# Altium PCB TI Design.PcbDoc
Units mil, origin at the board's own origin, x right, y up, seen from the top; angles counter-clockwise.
Board outline 3200 x 1800 mil, 4 copper layers (Top Layer, GND, Power Supply, Bottom Layer), stack 90 mil thick; 62 components, 53 nets, 248 pads, 98 vias.
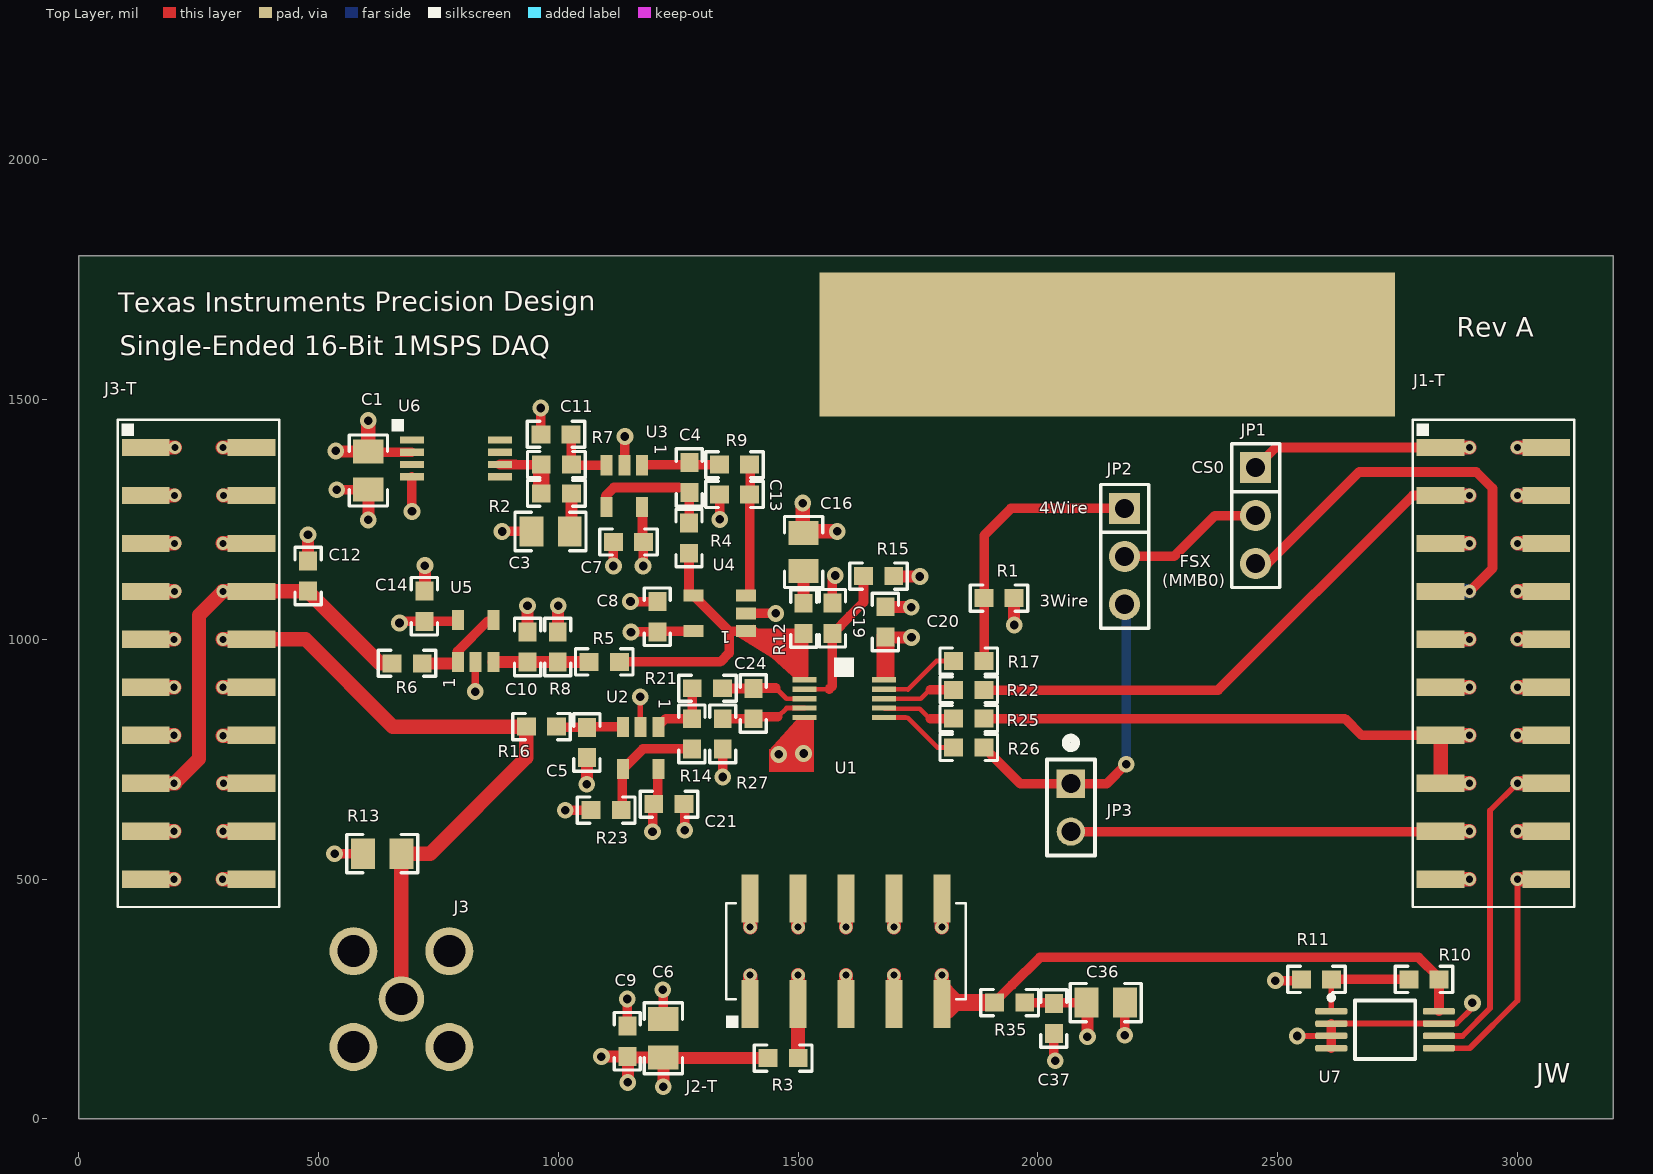
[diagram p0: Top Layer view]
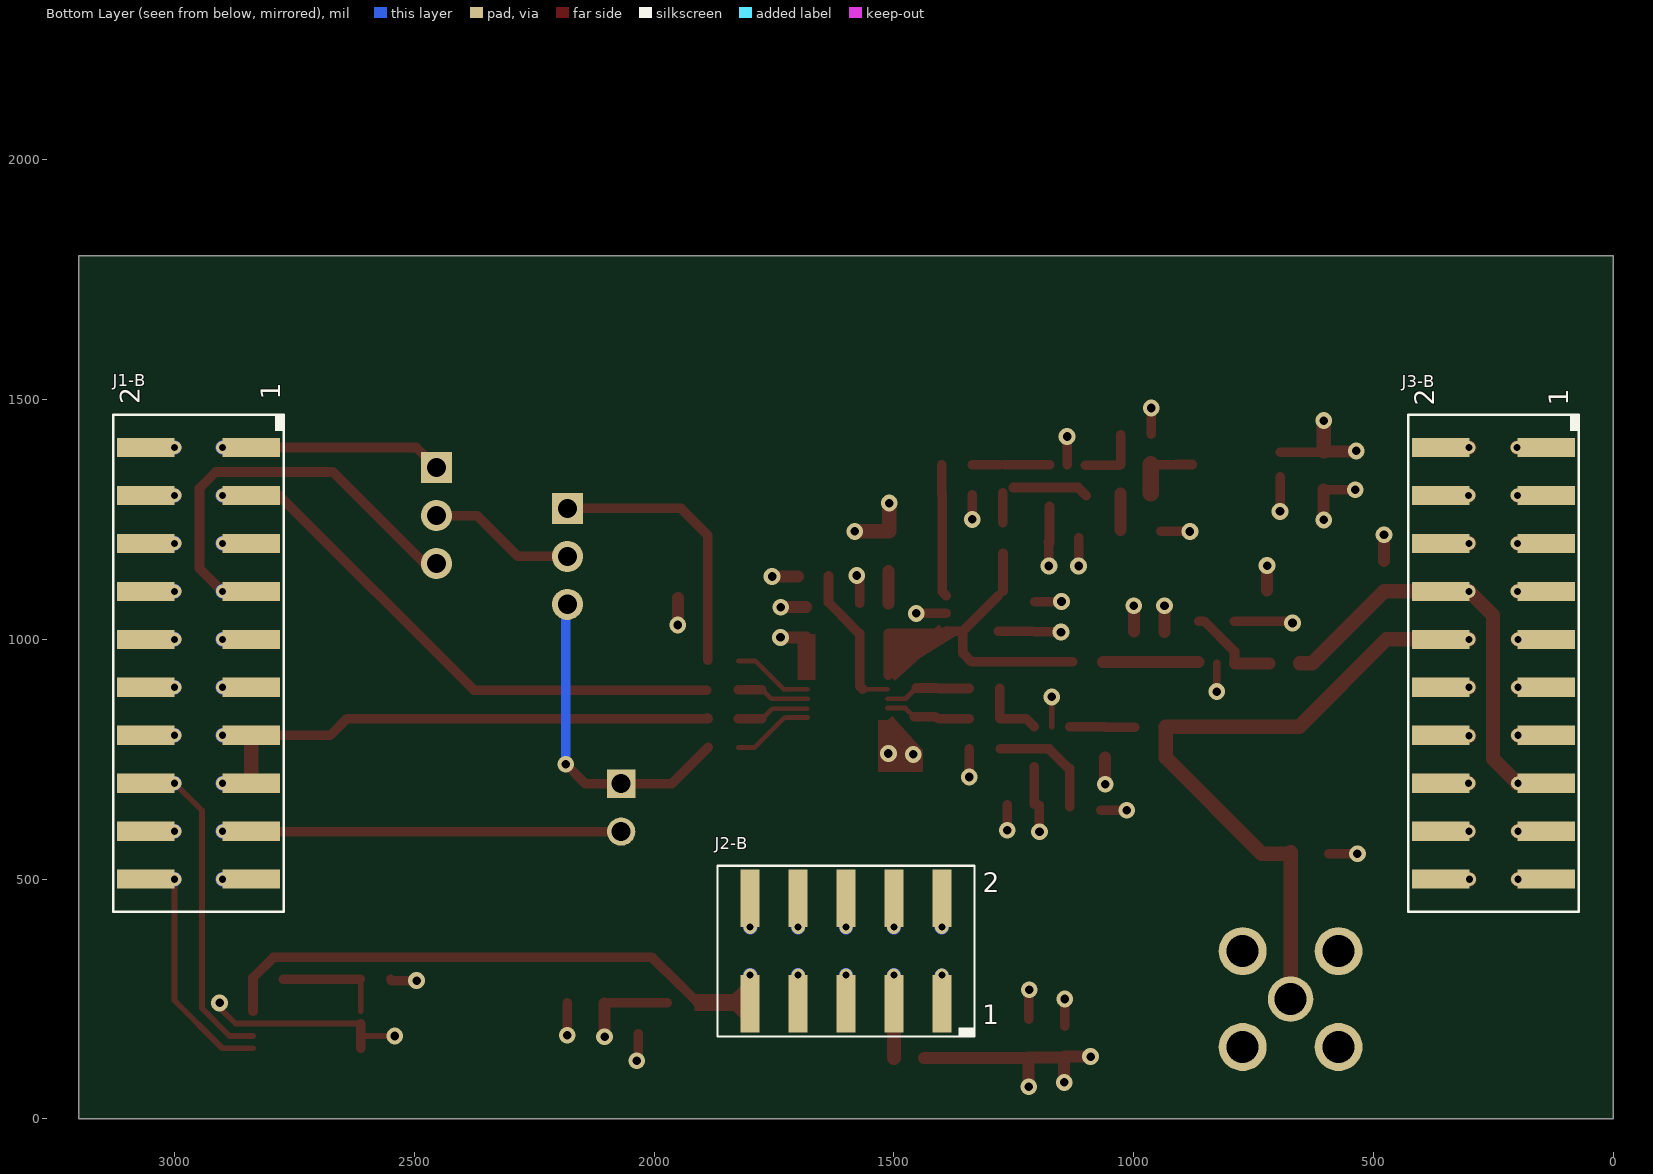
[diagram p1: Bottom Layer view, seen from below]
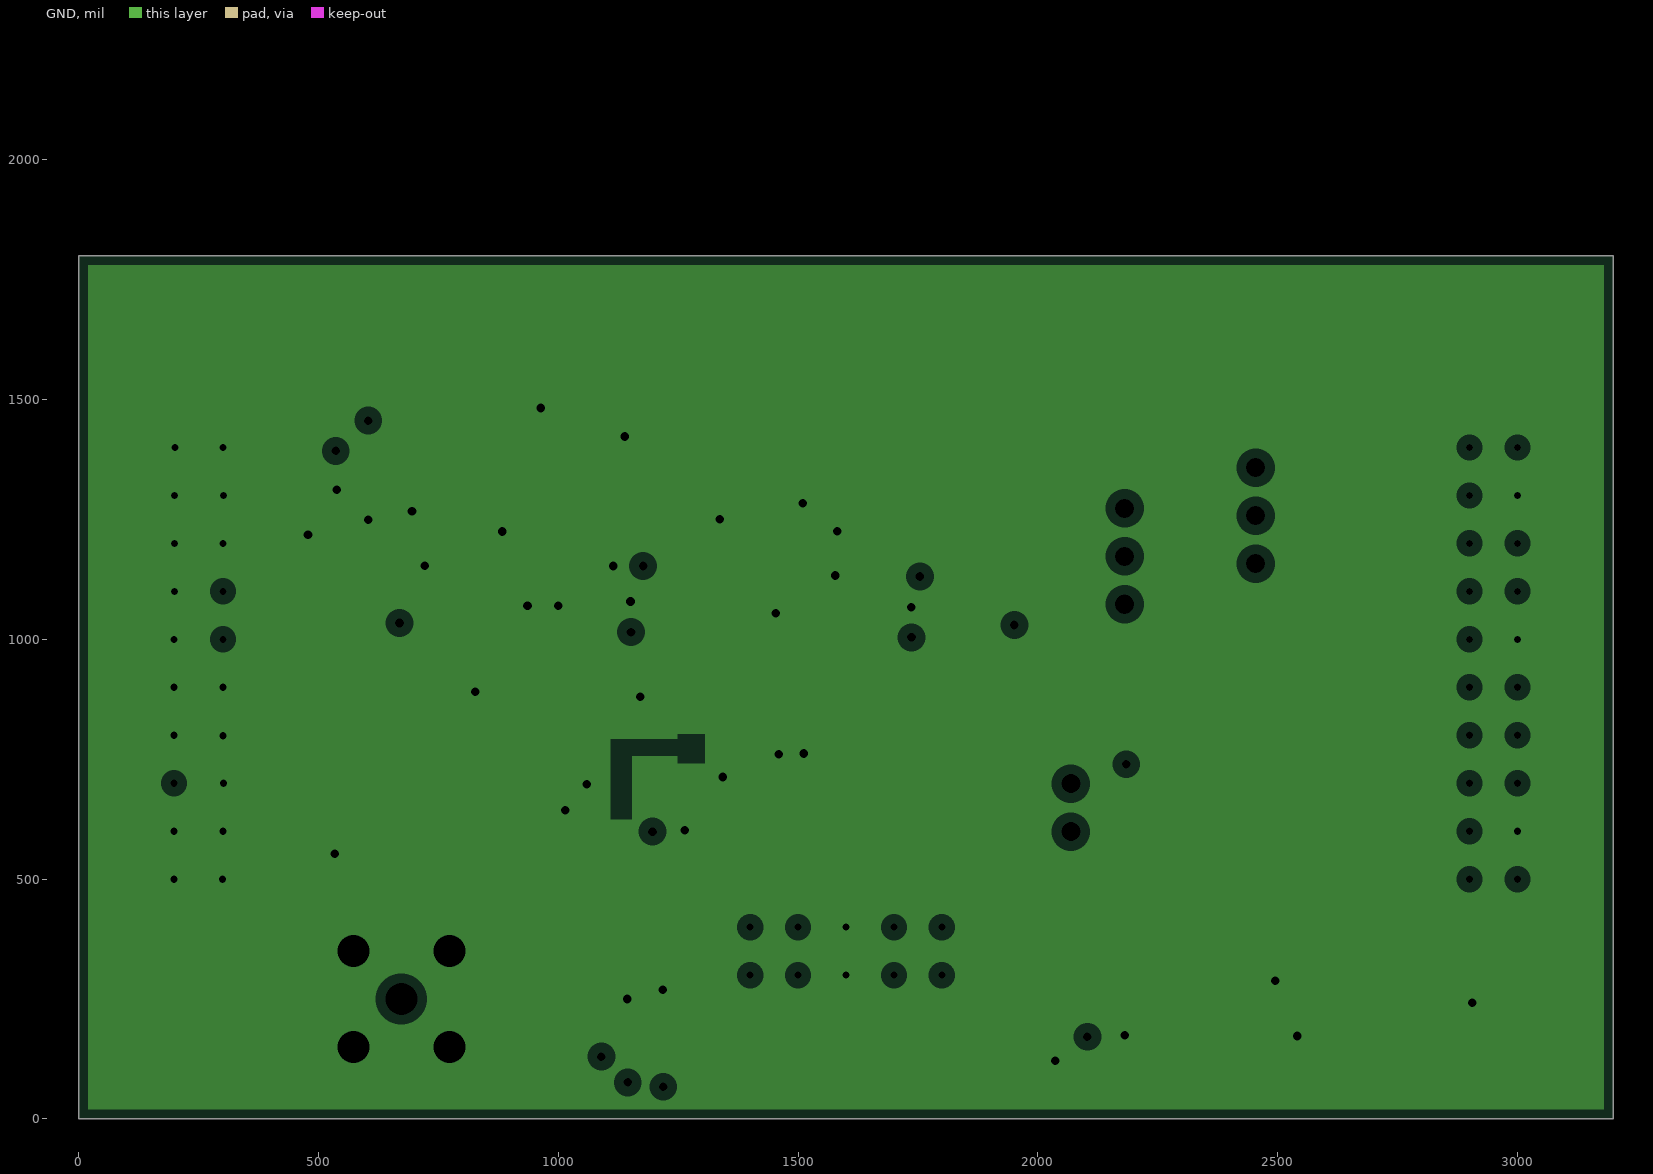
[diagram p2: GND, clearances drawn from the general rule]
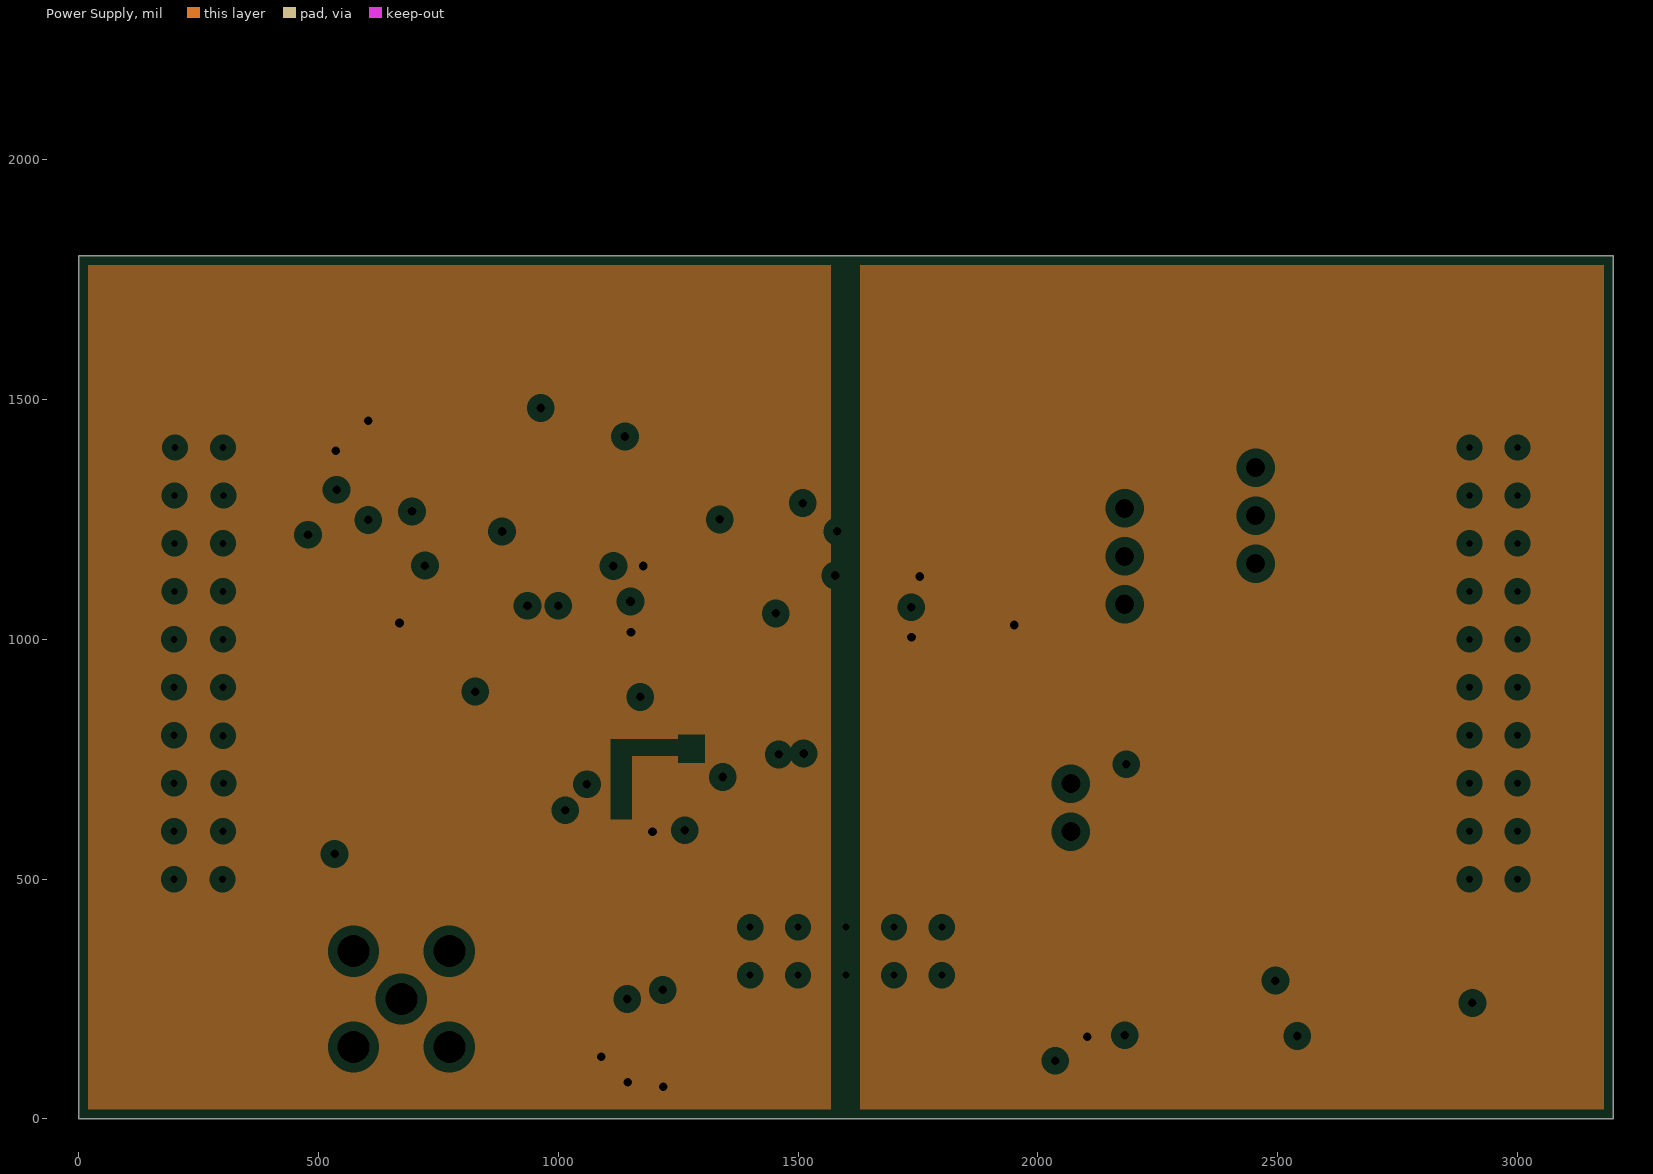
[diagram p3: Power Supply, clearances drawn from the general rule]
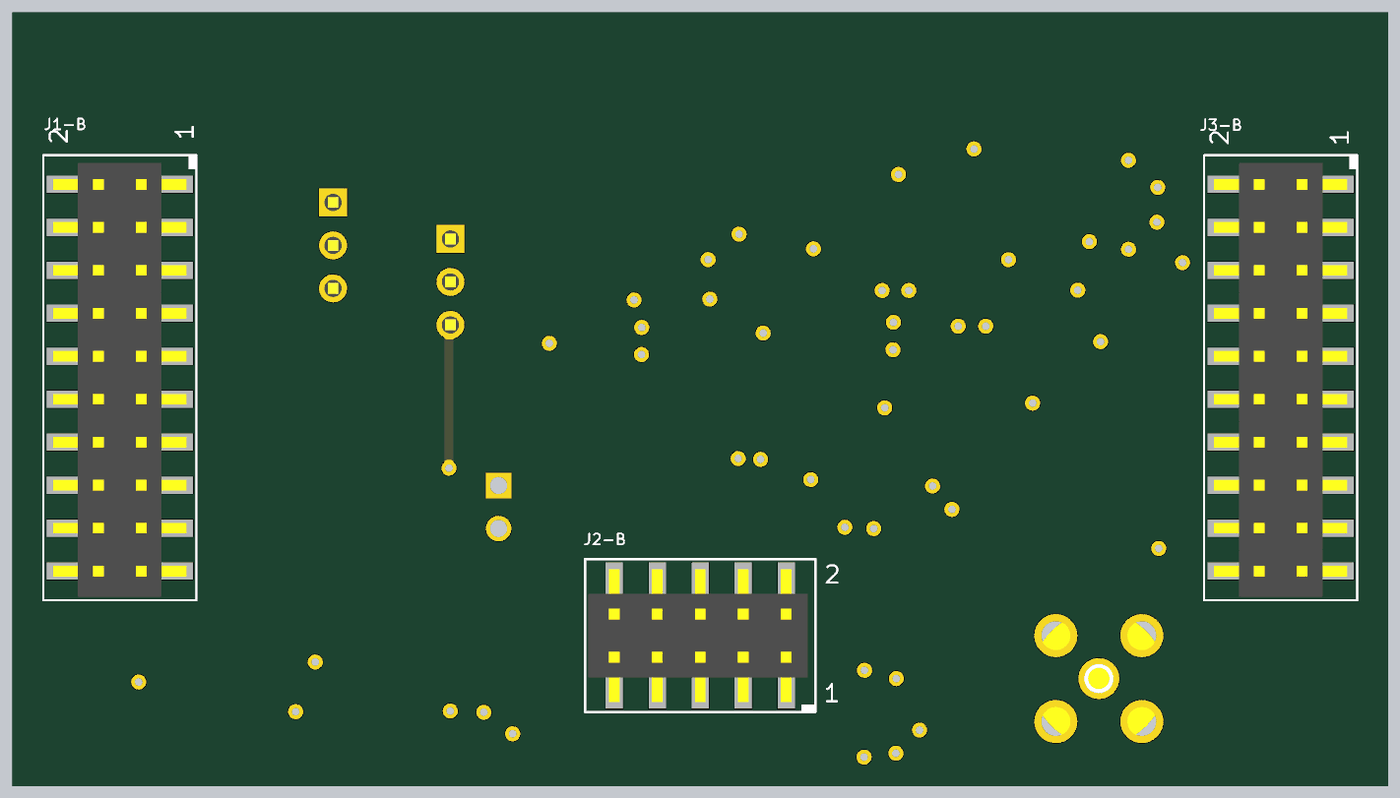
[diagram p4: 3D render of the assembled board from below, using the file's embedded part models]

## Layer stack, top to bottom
Top Layer: signal copper 1.4
Dielectric: core 59.2, FR-4, Dk 4.8
GND: plane copper 1.4, net GND
Dielectric: prepreg 12.6, FR-4, Dk 4.8
Power Supply: plane copper 1.4, net (Multiple Nets)
Dielectric: core 12.6, FR-4, Dk 4.8
Bottom Layer: signal copper 1.4

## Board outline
0,0 0,1800 3200,1800 3200,0 0,0

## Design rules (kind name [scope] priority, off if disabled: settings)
AcuteAngle [All] p1: minimum=4.50000000000000E+0001 checktracksonly=FALSE
AssemblyTestPointUsage [All] p1: valid=2
Clearance Clearance_BoardEdge_MountingHoles [OnCopper and InComponentClass('Mounting Holes') vs IsKeepOut] p1: gap=40
Clearance Clearance_BoardEdge_Poly [OnCopper and InPoly vs IsKeepOut] p2: gap=25
Clearance Clearance_BoardEdge [OnCopper and Not InComponentClass('Logo') and not InComponentClass('FiducialMark') and not InRegion(1000,500,4000,800) and Not IsKeepout vs IsKeepOut] p3: gap=75
Clearance Clearance_Poly [InPolygon] p4: gap=25
Clearance [All] p5: gap=8
ComponentClearance ComponentClearance_Shunt [InComponentClass('Header') vs InComponentClass('Shunt')] p1: gap=0 collisioncheckmode=3 verticalgap=0 showdistances=FALSE
ComponentClearance ComponentClearance_Logo [InComponentClass('Logo')] p2: gap=50 collisioncheckmode=3 verticalgap=10 showdistances=FALSE
ComponentClearance ComponentClearance_ScrewToNut [(HasFootprint('NY PMS 440 0025 PH')) vs (HasFootprint('Keystone_1902C'))] p3: gap=5 collisioncheckmode=3 verticalgap=10 showdistances=FALSE
ComponentClearance ComponentClearance_MountingHoles [InComponentClass('Mounting Holes')] p4: gap=250 collisioncheckmode=3 verticalgap=100000 showdistances=FALSE
ComponentClearance ComponentClearance_SmallPassives [HasFootprint('0201*') or HasFootprint('0402*') or HasFootprint('0508') or HasFootprint('0603*') or HasFootprint('0612') or HasFootprint('0805*') or HasFootprint('0815*') or HasFootprint('0830*') or HasFootprint('1206*') or HasFootprint('1210*') or HasFootprint('1808*') or HasFootprint('1812*') or HasFootprint('1825*') or HasFootprint('2010*') or HasFootprint('2220*') or HasFootprint('2225*') or HasFootprint('2512*') or HasFootprint('2728*') or HasFootprint('3518*') vs HasFootprint('0201*') or HasFootprint('0402*') or HasFootprint('0508') or HasFootprint('0603*') or HasFootprint('0612') or HasFootprint('0805*') or HasFootprint('0815*') or HasFootprint('0830*') or HasFootprint('1206*') or HasFootprint('1210*') or HasFootprint('1808*') or HasFootprint('1812*') or HasFootprint('1825*') or HasFootprint('2010*') or HasFootprint('2220*') or HasFootprint('2225*') or HasFootprint('2512*') or HasFootprint('2728*') or HasFootprint('3518*')] p5: gap=20 collisioncheckmode=3 verticalgap=10 showdistances=FALSE
ComponentClearance ComponentClearance_THtoSMT [IsThruComponent vs IsSMTComponent] p6: gap=100 collisioncheckmode=3 verticalgap=30 showdistances=FALSE
ComponentClearance ComponentClearance_THtoTH [IsThruComponent vs IsThruComponent] p7: gap=118.11 collisioncheckmode=3 verticalgap=30 showdistances=FALSE
ComponentClearance [All] p8 off: gap=40 collisioncheckmode=3 verticalgap=10 showdistances=FALSE
DiffPairsRouting [All] p1: maxlimit=100 minlimit=10 mostfreqgap=10 maxuncoupledlength=1000
FabricationTestPointUsage TestPointUsage [All] p1: valid=2 allowmultiple=FALSE
FabricationTestpoint Testpoint [All] p1: side=3 testpointundercomponent=TRUE minsize=40 maxsize=100 preferedsize=60 minholesize=0 maxholesize=40 preferedholesize=32 testpointgrid=1 allowsidetop=TRUE allowsidebottom=TRUE usegrid=TRUE gridtolerance=0.01
FanoutControl Fanout_LCC [IsLCC] p1: bgadir=Out bgaviamode=Centered fanoutstyle=Auto fanoutdirection=Alternating viagrid=1 // Fanout_LCC (Default Rule)
FanoutControl Fanout_BGA [IsBGA] p2: bgadir=Out bgaviamode=Centered fanoutstyle=Auto fanoutdirection=Alternating viagrid=1 // Fanout_BGA (Default Rule)
FanoutControl Fanout_Default [All] p4: bgadir=Out bgaviamode=Centered fanoutstyle=Auto fanoutdirection=Alternating viagrid=1 // Fanout_Default (Default Rule)
FanoutControl Fanout_Small [(CompPinCount < 5)] p5: bgadir=Out bgaviamode=Centered fanoutstyle=Auto fanoutdirection=OutThenIn viagrid=1 // Fanout_Small (Default Rule)
HoleSize [All] p1: absolutevalues=TRUE maxlimit=251 minlimit=7.8 maxpercent=80.000 minpercent=20.000
MinimumAnnularRing MinimumAnnularRing_ThermalPadVias [IsVia and InAnyComponent] p1: minimumring=5.91
MinimumAnnularRing [All] p2: minimumring=6
MinimumSolderMaskSliver MinimumSolderMaskSliver_Logo [InComponentClass('Logo') vs InComponentClass('Logo')] p1: minsoldermaskwidth=0.7
MinimumSolderMaskSliver [All] p2: minsoldermaskwidth=3.94
PlaneClearance [All] p1: clearance=20
PlaneConnect [All] p1: planeconnectstyle=Direct reliefexpansion=10 reliefentries=4 reliefconductorwidth=10 reliefairgap=10
PolygonConnect [All] p1: connectstyle=Relief reliefconductorwidth=10 reliefentries=4 polygonreliefangle="90 Angle" airgapwidth=10
RoutingVias ThermalPadVias [IsVia and InAnyComponent] p1: holewidth=18 width=35 viastyle="Through Hole" minholewidth=7.87 minwidth=19.68 maxholewidth=20 maxwidth=40
RoutingVias [All] p2: holewidth=18 width=35 viastyle="Through Hole" minholewidth=7.87 minwidth=20 maxholewidth=40 maxwidth=65
SMDToCorner [All] p1: distance=30000
SilkToSilkClearance [All] p1: silktosilkclearance=5
SilkscreenOverComponentPads [All] p1: minsilkscreentomaskgap=5
SolderMaskExpansion [All] p1: expansion=1.97
Width [All] p1: maxlimit=100 minlimit=6 preferedwidth=10 checkconnectedcopper=TRUE
13 further rules are at their usual default settings.

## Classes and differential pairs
component class Logo: Logo1 "Texas Instruments Precision Design"
component class Header: JP1 JP2

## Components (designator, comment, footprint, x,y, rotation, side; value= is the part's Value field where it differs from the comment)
C1 "C0805C105K8RACTU" 0805_HV 604,1352 r270 top
C3 "GRM21BR70J106KE76L" 0805_HV 984,1225 r180 top
C4 "GRM188R70J105KA01D" 0603 1273.34,1337.48 r270 top
C5 "GRM1885C1E102JA01D" 0603 1059.68,785.05 r270 top
C6 "GRM21BR61E106MA73" 0805_HV 1219,168 r90 top
C7 "0603YC104JAT2A" 0603 1146.57,1203 r180 top
C8 "0603YC104JAT2A" 0603 1206.68,1047.05 r90 top
C9 "C0603C102J5GAC" 0603 1144,162 r270 top
C10 "GRM188R70J105KA01D" 0603 936,984 r270 top
C11 "GRM188R70J105KA01D" 0603 995.5,1427.45 r0 top
C12 "GRM188R70J105KA01D" 0603 478.32,1132 r270 top
C13 "GRM188R70J105KA01D" 0603 1367.68,1302.05 r0 top
C14 "0603YC104JAT2A" 0603 721,1069 r90 top
C16 "GRM21BR71A106KE51L" 0805_HV 1511.68,1182.05 r270 top
C19 "GRM188R71E105KA12D" 0603 1571.68,1044.05 r270 top
C20 "GRM188R71E105KA12D" 0603 1682.08,1036.5 r270 top
C21 "0603YC104JAT2A" 0603 1230.68,656.25 r0 top
C24 "GRM1885C1E102JA01D" 0603 1406.68,866.05 r270 top
C36 "GRM21BR61E106MA73" 0805_HV 2141.3,242.55 r0 top
C37 "C0603C102J5GAC" 0603 2033.3,209.55 r90 top
J1-B "Bottom Side Connector" CONN_SSW-110-22-F-D-VS-K 2950,950 r90 bottom
J1-T "TSM-110-01-T-DV-P" CONN_TSM-110-01-T-DV-P 2950,950 r270 top
J2-B "SSW-105-22-F-D-VS-K" CONN_SSW-105-22-F-D-VS-K 1600,350 r180 bottom
J2-T "TSM-105-01-T-DV-P" CONN_TSM-105-01-T-DV-P 1600,350 r0 top
J3 "142-0701-201" Johnson_142-0701-20x 673,250 r0 top
J3-B "Bottom Side Connector" CONN_SSW-110-22-F-D-VS-K 250,950 r90 bottom
J3-T "TSM-110-01-T-DV-P" CONN_TSM-110-01-T-DV-P 250,950 r270 top
JP1 "PBC03SAAN" PBC03SAAN 2454,1258 r270 top
JP2 "PBC03SAAN" PBC03SAAN 2181,1173 r270 top
JP3 "5-146261-1" CONN_5-146261-1 2068.82,649.18 r270 top
R1 "CRCW060320K0FKEA" 0603 1919,1086 r180 top
R2 "CRCW060320K0FKEA" 0603 996,1304.46 r0 top
R3 "ERJ-3GEY0R00V" 0603 1469,127 r180 top
R4 "CRCW060320K0FKEA" 0603 1272.68,1211.05 r90 top
R5 "RG1608P-102-B-T5" 0603 1096,953 r0 top
R6 "RG1608P-102-B-T5" 0603 685,950 r0 top
R7 "RG1608P-102-B-T5" 0603 996,1364.46 r0 top
R8 "RG1608P-102-B-T5" 0603 999,984 r270 top
R9 "RG1608P-102-B-T5" 0603 1367.69,1364.22 r0 top
R10 "Uninstalled" 0603 2805,291 r0 top
R11 "RC0603FR-0747RL" 0603 2581,291 r180 top
R12 "ERJ-3RQFR22V" 0603 1511.68,1043.65 r270 top
R13 "RG2012P-510-B-T5" 0805_HV 633,553 r0 top
R14 "RC0603FR-0710RL" 0603 1278.68,803.05 r90 top
R15 "RC0603FR-0710RL" 0603 1668,1132 r0 top
R16 "RC0603FR-0710RL" 0603 965,818 r0 top
R17 "RC0603FR-0710RL" 0603 1856,954.7 r0 top
R21 "RC0603FR-0710RL" 0603 1311,898 r0 top
R22 "RC0603FR-0710RL" 0603 1856,894.7 r0 top
R23 "RC0603FR-0710RL" 0603 1100,644 r0 top
R25 "RC0603FR-0710RL" 0603 1856,834.7 r0 top
R26 "RC0603FR-0710RL" 0603 1856,774.7 r0 top
R27 "RC0603FR-0710RL" 0603 1343,803 r90 top
R35 "ERJ-3GEY0R00V" 0603 1941.3,242.55 r0 top
"Texas Instruments Precision Design" "Texas Instruments" TI_Stacked_SolderMask_Medium 2145,1615 r0 top (schematic designator Logo1)
U1 "ADS886XIDGS" DGS_10P2 1595.68,876.75 r0 top
U2 "OPA320AIDBV" SOT23-5P 1172,772 r270 top
U3 "OPA333AIDBV" SOT23-5P 1138,1318 r270 top
U4 "THS4281DBV" DBV-5 1336.68,1054.05 r180 top
U5 "OPA333AIDBV" SOT23-5P 828,998 r90 top
U6 "REF50XXAIDGK" DGK8 785,1376.8 r0 top
U7 "24LC256-I/ST" TSSOP-8 2724,186 r0 top

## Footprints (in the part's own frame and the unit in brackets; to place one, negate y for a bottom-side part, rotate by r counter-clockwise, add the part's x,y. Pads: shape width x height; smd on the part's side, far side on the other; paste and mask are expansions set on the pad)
0603 [mm] "0603 from SM-752 data"
  rect 1x0.95 smd: 1(-0.8,0) 2(0.8,0)
  silkscreen extent -1.52,-0.69 1.52,0.69, body extent -0.87,-0.47 0.87,0.47, height 0.85
0805_HV [mil] "0805 with 30mil clearance between pads"
  rect 50x63 smd: 1(-40,0) 2(40,0)
  silkscreen extent -74,-40 74,40, body extent -43,-29 43,29, height 43
CONN_5-146261-1 [mm] "Sullins"
  rect 1.5x1.5 hole 1.016: 1(-1.27,0)
  round 1.5 hole 1.016: 2(1.27,0)
  silkscreen extent -3.68,-1.27 2.54,1.27, body extent -2.51,-1.27 2.51,1.27, height 10.87
CONN_SSW-105-22-F-D-VS-K [mil]
  rect 40x120 smd: 1(200,-110) 2(200,110) 3(100,-110) 4(100,110) 5(0,-110) 6(0,110) 7(-100,-110) 8(-100,110) 9(-200,-110) 10(-200,110)
  silkscreen extent -268,-178 268,178, body extent -260,-155 250,155, height 435
CONN_SSW-110-22-F-D-VS-K [mil]
  rect 40x120 smd: 1(450,-110) 2(450,110) 3(350,-110) 4(350,110) 5(250,-110) 6(250,110) 7(150,-110) 8(150,110) 9(50,-110) 10(50,110) 11(-50,-110) 12(-50,110) 13(-150,-110) 14(-150,110) 15(-250,-110) 16(-250,110) 17(-350,-110) 18(-350,110) 19(-450,-110) 20(-450,110)
  silkscreen extent -518,-178 518,178, body extent -510,-155 500,155, height 435
CONN_TSM-105-01-T-DV-P [mil]
  rect 36x100 smd mask+2: 1(-200,-110) 2(-200,110) 3(-100,-110) 4(-100,110) 5(0,-110) 6(0,110) 7(100,-110) 8(100,110) 9(200,-110) 10(200,110)
  silkscreen extent -250,-160 250,100, body extent -250,-145 250,145, height 380
CONN_TSM-110-01-T-DV-P [mil]
  rect 36x100 smd mask+2: 1(-450,-110) 2(-450,110) 3(-350,-110) 4(-350,110) 5(-250,-110) 6(-250,110) 7(-150,-110) 8(-150,110) 9(-50,-110) 10(-50,110) 11(50,-110) 12(50,110) 13(150,-110) 14(150,110) 15(250,-110) 16(250,110) 17(350,-110) 18(350,110) 19(450,-110) 20(450,110)
  silkscreen extent -508,-168 508,168, body extent -500,-145 500,145, height 380
DBV-5 [mil]
  rect 42x25 smd: 1(-54.5,37) 2(-54.5,0) 3(-54.5,-37) 4(54.5,-37) 5(54.5,37)
DGK8 [mil]
  rect 50x15 smd: 1(-90.2,39) 2(-90.2,13.4) 3(-90.2,-12.2) 4(-90.2,-37.8) 5(93.4,-37.8) 6(93.4,-12.2) 7(93.4,13.4) 8(93.4,39)
  silkscreen extent -132,57 -107,82
DGS_10P2 [mil]
  rect 50x11 smd: 1(-82,39) 2(-82,19.3) 3(-82,-0.4) 4(-82,-20.1) 5(-82,-39.8) 6(84,-39.8) 7(84,-20.1) 8(84,-0.4) 9(84,19.3) 10(84,39)
  silkscreen extent -20,45 20,85
Johnson_142-0701-20x [mil] "Johnson Components recommended land pattern"
  round 95 hole 67: 1(0,0)
  round 100 hole 67: 2(100,100) 3(100,-100) 4(-100,-100) 5(-100,100)
  body extent -156,-156 156,156, height 375
PBC03SAAN [mm] "Sullins 100mil, 1x3, 230 mil above insulator"
  rect 1.65x1.65 hole 1.016: 1(-2.54,0)
  round 1.65 hole 1.016: 2(0,0) 3(2.54,0)
  silkscreen extent -3.81,-1.27 3.81,1.27, body extent -3.81,-1.27 3.81,1.27, height 8.38
SOT23-5P [mil]
  rect 42x25 smd: 1(-45,37) 2(-45,0) 3(-45,-37) 4(42,-37) 5(42,37)
TI_Stacked_SolderMask_Medium [mil]
  rect 1200x300 smd paste-196 mask-196: 0(0,0)
TSSOP-8 [mm] "TSSOP, 8-Leads, Body 3.1x4.5mm (max), Pitch 0.65mm, IPC Medium Density"
  rrect50% 1.7x0.35 smd: 1(-2.85,0.975) 2(-2.85,0.325) 3(-2.85,-0.325) 4(-2.85,-0.975) 5(2.85,-0.975) 6(2.85,-0.325) 7(2.85,0.325) 8(2.85,0.975)
  silkscreen extent -2.97,-1.55 1.6,1.82, body extent -3.2,-1.55 3.2,1.55, height 1.07

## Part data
C1: "CAP, CERM, 1uF, 10V, +/-10%, X7R, 0805"
C3: "CAP, CERM, 10uF, 6.3V, +/-10%, X7R, 0805"
C4 C10 C11 C12 C13: "CAP, CERM, 1uF, 6.3V, +/-10%, X7R, 0603"
C5 C24: "CAP, CERM, 1000pF, 25V, +/-5%, C0G/NP0, 0603"
C6 C36: "CAP, CERM, 10uF, 25V, +/-20%, X5R, 0805"
C7 C8 C14 C21: "CAP, CERM, 0.1uF, 16V, +/-5%, X7R, 0603"
C9 C37: "CAP, CERM, 1000pF, 50V, +/-5%, C0G/NP0, 0603"
C16: "CAP, CERM, 10uF, 10V, +/-10%, X7R, 0805"
C19 C20: "CAP, CERM, 1uF, 25V, +/-10%, X7R, 0603"
J1-B J3-B: library part SSW-110-22-F-D-VS-K, "Connector, Receptacle, 100mil, 10x2, Gold plated, SMD"
J1-T J3-T: "Header, 100mil, 10x2, SMD"
J2-B: "Connector, Header, 10-Pos (10x2), Receptacle, 100x100-mil Pitch"
J2-T: "Header, 100mil, 5x2, SMD"
J3: "Connector, TH, SMA"
JP1 JP2: "Header, TH, 100mil, 1x3, Gold plated, 230 mil above insulator"
JP3: "Header, 100mil, 2x1, Gold plated, TH"
R1 R2 R4: "RES, 20.0k ohm, 1%, 0.1W, 0603"
R3 R35: "RES, 0 ohm, 5%, 0.1W, 0603"
R5 R6 R7 R8 R9: "RES, 1.00k ohm, 0.1%, 0.1W, 0603"
R10: library part ERJ-3GEY0R00V
R11: "RES, 47.0 ohm, 1%, 0.1W, 0603"
R12: "RES, 0.22 ohm, 1%, 0.1W, 0603"
R13: "RES, 51 ohm, 0.1%, 0.125W, 0805"
R14 R15 R16 R17 R21 R22 R23 R25 R26 R27: "RES, 10.0 ohm, 1%, 0.1W, 0603"
"Texas Instruments Precision Design": library part TI_Logo, "Texas Instrument Corporate Signature"
U1: "IC, 16 Bit 1 MSPS, Serial Interface"
U2: library part OPA333AIDBV, "IC, 1.8V, microPower, CMOS Op Amp, Zer?Drift Series"
U3 U5: "IC, 1.8V, microPower, CMOS Op Amp, Zer?Drift Series"
U4: "IC, Very Low-Power, High-Speed, R-R In/Output Op-Amp"
U6: "IC, Precision Voltage Reference, xxV,"

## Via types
v1: diameter 28, hole 15, Top Layer to Bottom Layer, 50 vias
v2: diameter 35, hole 18, Top Layer to Bottom Layer, 48 vias

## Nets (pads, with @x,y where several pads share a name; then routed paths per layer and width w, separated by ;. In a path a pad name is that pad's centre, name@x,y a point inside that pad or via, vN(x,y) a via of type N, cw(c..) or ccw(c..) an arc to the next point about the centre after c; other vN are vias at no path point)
+3.3VD: J2-B.9 J2-T.9 R10.2 R35.1 U7.8 | length 1173.7
  Top Layer w20: R35.1 1909.8,243.4 1945.65,279.25 1946.5,279.25 2004.25,337 2794,337 2836.5,294.5 R10.2 U7.8@2836.5,224.68
  Top Layer w30: J2-T.9 v1(1800,300)
  Bottom Layer w30: J2-B.9 v1(1800,300)
+5VA: J2-B.3 J2-T.3 R3.1 | length 232.5
  Top Layer w30: R3.1@1500,127.5 J2-T.3 v1(1500,300)
  Bottom Layer w30: J2-B.3 v1(1500,300)
AVDD: C1.1 C6.1 C7.1 C8.1 C9.2 C14.1 C21.1 R3.2 U2.5 U3.5 U4.5 U5.5 U6.2 | length 1177.4
  Top Layer w20: v2(536,1393) v2@537,1392 ; C1.1 605.8,1390.2 U6.2 ; v2@672.5,1037.5 C14.1 ; C14.1@721.5,1038 U5.5@790,1038 ; C9.2@1144,129.69 C9.2@1145,129.69 ; v2@1152.18,1015.56 C8.1 ; C7.1@1175.68,1200 U3.5@1175.68,1277.05 ; v2(1177,1153) 1177,1201.93 C7.1 ; v2(1196.68,599.05) C21.1@1196.68,653.75 ; C21.1@1207.68,656.25 U2.5@1207.68,734.25 ; C8.1@1212.22,1017.05 U4.5
  Top Layer w25: v2@537,1392 C1.1 ; v2@1090.5,130.5 C9.2 ; v2(1145,76.22) C9.2@1145,128.48 ; C9.2@1145.48,128 C6.1 ; v2(1219,67.2) C6.1@1219,121.2 ; C6.1@1220,127 R3.2
  Top Layer w30: C1.1 v2(604,1456)
  other v2: 1090,130 1151.68,1015.05 669,1034
CONVST: JP2.3 JP3.1 R26.2 | length 678.2
  Top Layer w20: R26.2 1963.02,699.18 JP3.1 2143.83,699.18 v2(2184.33,739.68)
  Bottom Layer w20: v2(2184.33,739.68) JP2.3@2184.33,1073
CS0: J1-B.1 J1-T.1 JP1.1 | length 523.4
  Top Layer w20: JP1.1 2496,1400 J1-T.1
  Top Layer w30: J1-T.1 v1(2900,1400)
  Bottom Layer w30: J1-B.1 v1(2900,1400)
CS0/FSX: JP1.2 JP2.2 | length 308.2
  Top Layer w20: JP2.2 2284,1173 2369,1258 JP1.2
DVDD: C20.2 C36.1 C37.2 R1.1 R15.2 R35.2 U1.10 | length 360.1
  Top Layer w20: R35.2 C36.1
  Top Layer w25: C20.2@1683.04,1004.05 v2(1736.68,1004.05) ; R15.2@1700.5,1131 v2(1754,1131) ; v2@1950.5,1030.5 R1.1 ; v2(2103.3,171.55) C36.1@2103.3,240.55
  other v2: 1951,1030
FSX: J1-B.7 J1-T.7 JP1.3 | length 917.1
  Top Layer w20: JP1.3@2479,1158 2670,1349 2914,1349 2948,1315 2948,1148 v1(2900,1100) J1-T.7
  Bottom Layer w30: J1-B.7 v1(2900,1100)
GND: C1.2 C3.2 C5.2 C6.2 C7.2 C8.2 C9.1 C10.1 C11.1 C12.1 C13.1 C14.2 C16.1 C19.1 C20.1 C21.2 C36.2 C37.1 J1-B.4 J1-B.10 J1-B.18 J1-T.4 J1-T.10 J1-T.18 J2-B.5 J2-B.6 J2-T.5 J2-T.6 J3-B.1 J3-B.2 J3-B.3 J3-B.4 J3-B.5 J3-B.6 J3-B.7 J3-B.9 J3-B.11 J3-B.12 J3-B.13 J3-B.14 J3-B.16 J3-B.17 J3-B.18 J3-B.19 J3-B.20 J3-T.1 J3-T.2 J3-T.3 J3-T.4 J3-T.5 J3-T.6 J3-T.7 J3-T.9 J3-T.11 J3-T.12 J3-T.13 J3-T.14 J3-T.16 J3-T.17 J3-T.18 J3-T.19 J3-T.20 J3.2 J3.3 J3.4 J3.5 R8.1 R11.2 R13.1 R23.1 R27.1 U1.5 U2.2 U3.2 U4.2 U5.2 U6.4 U7.2 U7.3 U7.4 U7.7 | length 4071.4
  Top Layer w12: U2.2@1171,818 v2(1171,880) ; v2(2541,173) 2541.2,173.2 U7.3 ; U7.2 U7.7 2872.8,198.8 2906,232 v2(2906,242)
  Top Layer w15: v2(827,891) U5.2@827,951
  Top Layer w20: v2@533.93,553 R13.1 ; v2(538,1312) C1.2 ; v2(695,1266.8) U6.4@695,1339 ; v2@883.2,1225 C3.2 ; C11.1@963.5,1427.95 v2(963.5,1482.45) ; v2(1014.68,643.76) R23.1@1068.68,643.76 ; v2(1115.08,1153) C7.2@1115.08,1211.5 ; U3.2@1138.68,1364.05 v2@1138.68,1423 ; C9.1 v2(1144,250) ; v2@1151.18,1078.55 C8.2 ; C6.2 v2@1219,268.2 ; v2(1263.68,602.05) C21.2@1263.68,654.75 ; v2(1336.68,1250.05) C13.1@1336.68,1301.56 ; v2(1343,713) R27.1 ; U4.2 v2(1453.68,1054.05) ; C19.1 1571.68,1127.05 v2(1577.68,1133.05) ; v2@2033.3,124.55 C37.1 ; v2(2181.3,174.55) C36.2 ; v2(2495.3,288.55) 2547.06,288.55 R11.2 ; U7.4 U7.3 U7.2
  Top Layer w25: C12.1 v2(478.32,1218) ; v2(604,1249) C1.2 ; C14.2@722,1101.5 v2(722,1153.8) ; C10.1 v2(936,1070) ; R8.1@1000,1016.5 v2(1000,1070) ; v2(1059.68,698.05) C5.2 ; C20.1@1683.08,1067 v2(1736,1067)
  Top Layer w30: J3-T.9@124,1000 v1(199,1000) ; J3-T.19@125,500 v1@200,500 ; J3-T.17@125,600 v1@200,600 ; J3-T.13@125,800 v1@200,800 ; J3-T.11@125,900 v1@200,900 ; J3-T.7@125,1100 v1(200,1100) ; J3-T.5@125,1200 v1(200,1200) ; J3-T.3@125,1300 v1(200,1300) ; J3-T.1@126,1400 v1(201,1400) ; v1(300,500) J3-T.20@375,500 ; v1@300,799 J3-T.14@375,799 ; v1@300,900 J3-T.12@375,900 ; v1@300,1200 J3-T.6@375,1200 ; v1@300,1400 J3-T.2@375,1400 ; v1(301,600) J3-T.18@376,600 ; v1@301,700 J3-T.16@376,700 ; v1@301,1300 J3-T.4@376,1300 ; C16.1@1509.68,1225.05 v2(1509.68,1284.05) ; C16.1@1510.68,1225.05 v2(1581.68,1225.05) ; J2-T.5 v1(1600,300) ; v1(1600,400) J2-T.6 ; v1(3000,600) J1-T.18 ; v1(3000,1000) J1-T.10 ; v1(3000,1300) J1-T.4
  Bottom Layer w30: J2-B.5 v1(1600,300) ; v1(1600,400) J2-B.6 ; v1(3000,600) J1-B.18 ; v1(3000,1000) J1-B.10 ; v1(3000,1300) J1-B.4
  other v1: 199,500 199,600 302,700 301,799 199,800 199,900 301,900 301,1200 302,1300 301,1400
  other v2: 2036.3,121.55 1218,269.2 533.68,552.76 1459.68,760.05 1511.68,762.05 1150.68,1079.05 883,1224.8 1139,1423
J2-2: J1-B.2 J1-T.2 | length 120
  Top Layer w30: v1(3000,1400) J1-T.2
  Bottom Layer w30: v1(3000,1400) J1-B.2
J2-5: J1-B.5 J1-T.5 | length 120
  Top Layer w30: J1-T.5 v1(2900,1200)
  Bottom Layer w30: J1-B.5 v1(2900,1200)
J2-6: J1-B.6 J1-T.6 | length 120
  Top Layer w30: v1(3000,1200) J1-T.6
  Bottom Layer w30: v1(3000,1200) J1-B.6
J2-8: J1-B.8 J1-T.8 | length 120
  Top Layer w30: v1(3000,1100) J1-T.8
  Bottom Layer w30: v1(3000,1100) J1-B.8
J2-9: J1-B.9 J1-T.9 | length 120
  Top Layer w30: J1-T.9 v1(2900,1000)
  Bottom Layer w30: J1-B.9 v1(2900,1000)
J2-11: J1-B.11 J1-T.11 | length 120
  Top Layer w30: J1-T.11 v1(2900,900)
  Bottom Layer w30: J1-B.11 v1(2900,900)
J2-12: J1-B.12 J1-T.12 | length 120
  Top Layer w30: v1(3000,900) J1-T.12
  Bottom Layer w30: v1(3000,900) J1-B.12
J2-14: J1-B.14 J1-T.14 | length 120
  Top Layer w30: v1(3000,800) J1-T.14
  Bottom Layer w30: v1(3000,800) J1-B.14
J2-19: J1-B.19 J1-T.19 | length 120
  Top Layer w30: J1-T.19 v1(2900,500)
  Bottom Layer w30: J1-B.19 v1(2900,500)
J3-1: J2-B.1 J2-T.1 | length 120
  Top Layer w30: J2-T.1@1400,239 v1@1400,299
  Bottom Layer w30: J2-B.1@1400,239 J2-B.1@1400,299
  other v1: 1400,300
J3-2: J2-B.2 J2-T.2 | length 120
  Top Layer w30: v1(1400,400) J2-T.2
  Bottom Layer w30: v1(1400,400) J2-B.2
J3-4: J2-B.4 J2-T.4 | length 120
  Top Layer w30: v1(1500,400) J2-T.4
  Bottom Layer w30: v1(1500,400) J2-B.4
J3-7: J2-B.7 J2-T.7 | length 120
  Top Layer w30: J2-T.7 v1(1700,300)
  Bottom Layer w30: J2-B.7 v1(1700,300)
J3-8: J2-B.8 J2-T.8 | length 120
  Top Layer w30: v1(1700,400) J2-T.8
  Bottom Layer w30: v1(1700,400) J2-B.8
J3-10: J2-B.10 J2-T.10 | length 120
  Top Layer w30: v1(1800,400) J2-T.10
  Bottom Layer w30: v1(1800,400) J2-B.10
NetC3_1: C3.1 R2.2 | length 76
  Top Layer w25: C3.1@1027.5,1228.5 R2.2
NetC4_1: C4.1 R9.1 U3.1 | length 150
  Top Layer w20: U3.1@1175.68,1364.05 C4.1@1268.41,1364.05 ; C4.1@1278.98,1364.22 R9.1
NetC4_2: C4.2 R4.2 U3.4 | length 223
  Top Layer w20: 1098.68,1299.05 1116.15,1316.52 1251.69,1316.52 ; R4.2@1273.34,1243.21 C4.2
NetC5_1: C5.1 R16.2 U2.3 | length 134.2
  Top Layer w20: R16.2@997.95,816.55 C5.1 ; C5.1@1061.18,818.05 U2.3@1133.68,818.05
NetC10_2: C10.2 R5.1 R8.2 U5.3 | length 198.5
  Top Layer w25: U5.3@865.5,952.5 C10.2 R8.2 ; R8.2@999.5,953 R5.1
NetC11_2: C11.2 R7.2 U3.3 | length 134.5
  Top Layer w20: R7.2 C11.2@1027.5,1426.95 ; R7.2@1028.95,1363 U3.3
NetC13_2: C13.2 R9.2 U4.3 | length 276.5
  Top Layer w20: U4.3 1399.18,1099.05 C13.2 ; C13.2@1400.64,1302.05 R9.2@1400.64,1364.22
NetC16_2: C16.2 R12.1 | length 66.9
  Top Layer w25: R12.1 C16.2
NetC19_2: C19.2 R15.1 U1.2 | length 316.5
  Top Layer w10: U1.2 1564.98,896.05
  Top Layer w20: 1564.98,896.05 1571.68,902.75 C19.2 ; C19.2@1572.53,1012.56 1608.38,1048.41 1608.38,1049.26 1636.5,1077.38 R15.1
NetC24_1: C24.1 R21.2 U1.3 | length 174.9
  Top Layer w10: 1453.79,898.55 1475.98,876.35 U1.3
  Top Layer w20: R21.2@1342.95,897.55 C24.1 ; C24.1@1411.68,898.55 1453.79,898.55
NetC24_2: C24.2 R27.2 U1.4 | length 170.5
  Top Layer w10: 1457.68,838.25 1476.08,856.65 U1.4
  Top Layer w20: R27.2@1343.06,834.56 C24.2 ; C24.2@1414.38,838.25 1457.68,838.25
NetR4_1: R4.1 R5.2 R12.2 U1.1 U4.1 U4.4 | length 703.4
  Top Layer w20: R5.2 1338,953 1356.18,971.18 1356.18,1017.05 ; U4.4@1272.68,1100.55 R4.1 ; U4.4 1356.18,1017.05 ; U4.1 1356.18,1017.05 ; U4.1@1396.08,1012.16 R12.2 1511.68,925.05
NetR6_2: R6.2 U5.1 U5.4 | length 196.6
  Top Layer w20: U5.1@790,951 790,975 853,1038 U5.4@864,1038
  Top Layer w25: R6.2 U5.1@789,950
NetR10_1: R10.1 R11.1 U7.1 | length 227.9
  Top Layer w12: U7.1 2611.8,290.3 R11.1
  Top Layer w20: R11.1 R10.1
NetR14_1: R14.1 R23.2 U2.4 | length 241.2
  Top Layer w20: R23.2@1133.68,650.75 U2.4@1133.68,731.05 ; U2.4 1176.56,771.56 R14.1
NetR14_2: R14.2 R21.1 U2.1 | length 140.5
  Top Layer w20: U2.1@1207.68,818.05 1224.18,834.55 R14.2 ; R14.2@1279.5,835.37 R21.1
NetR17_1: R17.1 U1.9 | length 163.9
  Top Layer w10: U1.9 1725.68,896.05 ; 1729.33,895.68 1788.33,954.68 ; 1790,954.7 R17.1
NetR22_1: R22.1 U1.8 | length 147.2
  Top Layer w10: U1.8 1751.98,876.35 ; 1755.63,875.98 1774.33,894.68
  Top Layer w20: 1776,894.7 R22.1
NetR25_1: R25.1 U1.7 | length 146.8
  Top Layer w10: U1.7@1680.88,855.45 1750.28,855.45 ; 1753.93,855.08 1774.33,834.68
  Top Layer w20: 1776,834.7 R25.1
NetR26_1: R26.1 U1.6 | length 165.1
  Top Layer w10: U1.6 1724.78,836.95 ; 1728.43,836.58 1790.33,774.68 ; 1792,774.7 R26.1
REF_OUT: R2.1 R7.1 U6.6 | length 146.2
  Top Layer w20: U6.6 878.5,1364.5 910.86,1364.5 910.9,1364.46 R7.1
  Top Layer w35: R2.1 R7.1
SCL: J1-B.16 J1-T.16 U7.6 | length 743.3
  Top Layer w12: U7.6 2885.2,173.2 2943,231 2943,643 v1(3000,700)
  Top Layer w30: v1(3000,700) J1-T.16
  Bottom Layer w30: v1(3000,700) J1-B.16
SCLK: J1-B.3 J1-T.3 R22.2 | length 1237.7
  Top Layer w20: R22.2@1890.45,894 2376,894 2782,1300 J1-T.3
  Top Layer w30: J1-T.3 v1(2900,1300)
  Bottom Layer w30: J1-B.3 v1(2900,1300)
SDA: J1-B.20 J1-T.20 U7.5 | length 578
  Top Layer w12: U7.5 2900.61,147.61 3000,247 v1(3000,500)
  Top Layer w30: v1(3000,500) J1-T.20
  Bottom Layer w30: v1(3000,500) J1-B.20
SDI: JP2.1 R1.2 R17.2 | length 577.3
  Top Layer w20: R17.2@1887.83,956 1887.83,1216.83 1944,1273 JP2.1
SDO: J1-B.13 J1-B.15 J1-T.13 J1-T.15 R25.2 | length 1318.7
  Top Layer w20: R25.2 R25.2@1891,834.7 ; R25.2@1889,836.7 R25.2@1891,834.7 ; J1-T.13@2849,800 2675,800 2640.3,834.7 R25.2@1891,834.7
  Top Layer w30: v1(2900,700) J1-T.15 J1-T.13 v1(2900,800)
  Bottom Layer w30: J1-B.15 v1(2900,700) ; J1-B.13 v1(2900,800)
TOUT: J1-B.17 J1-T.17 JP3.2 | length 891.2
  Top Layer w20: JP3.2 J1-T.17@2840,599.18
  Top Layer w30: J1-T.17 v1(2900,600)
  Bottom Layer w30: J1-B.17 v1(2900,600)
VCM: C12.2 J3-B.8 J3-B.15 J3-T.8 J3-T.15 R6.1 | length 931.5
  Top Layer w30: J3-T.15@127,700 v1@202,700 ; v1@200,700 251,751 251,1050 v1(301,1100) ; v1@300,1100 J3-T.8@359,1100 ; J3-T.8 477.82,1100 627.82,950 R6.1
  other v1: 199,700
VIN: J3-B.10 J3-T.10 J3.1 R13.2 R16.1 | length 1422.9
  Top Layer w30: v1@300,1000 v1(301,1000) J3-T.10 473,1000 655,818 R16.1 933.5,753.5 733,553 R13.2 ; J3.1 R13.2@673,556
pads on no net: "Texas Instruments Precision Design.0" U6.1 U6.3 U6.5 U6.7 U6.8

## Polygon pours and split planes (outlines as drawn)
GND on GND (split plane): 3179.9,20.1 20.1,20.1 20.1,1779.9 3179.9,1779.9
DVDD on Power Supply (split plane): 3179.9,20.1 1629.09,20.1 1629.09,1779.9 3179.9,1779.9
AVDD on Power Supply (split plane): 1568.91,20.1 20.1,20.1 20.1,1779.9 1568.91,1779.9

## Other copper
Top Layer:
  region net GND: 1469.77,741.93 1533.68,814.05 1503.53,840.77 1439.62,768.65
  rectangle net GND: 1439.68,723.05 1524.68,771.05
  rectangle net GND: 1495.68,723.05 1533.68,832.05
  region net NetR4_1: 1413.26,1004.31 1513.09,978.98 1517.68,997.05 1417.84,1022.38
  rectangle net NetR4_1: 1499.68,998.05 1500.68,999.05
  region net NetR4_1: 1391.18,1002.47 1516.5,964.32 1520.68,978.05 1395.36,1016.19
  region net NetR4_1: 1378.12,1004.57 1506.07,948.03 1516.68,972.05 1388.73,1028.59
  region net NetR4_1: 1370.44,1007.57 1502.51,925.92 1514.91,945.98 1382.83,1027.62
  region net NetR4_1: 1389.1,1011.33 1498.68,913.05 1516.04,932.4 1406.46,1030.68
  rectangle net DVDD: 1663.68,915.75 1700.68,1011.05
  rectangle net +3.3VD: 1790,225 1916,261
  region net +3.3VD: 1800.34,270.85 1831.13,238.04 1844.99,251.04 1814.19,283.86
  region net +3.3VD: 1812.15,203.34 1844.96,234.13 1831.96,247.99 1799.14,217.19
GND (plane layer: these items are gaps in the copper):
  rectangle: 1140.68,757 1251.41,792.05
  region: 1153,625.32 1153,791.79 1109.68,791.79 1109.68,625.32
  rectangle: 1249.68,742.03 1305.88,802.05
Power Supply (plane layer: these items are gaps in the copper):
  rectangle: 1109.68,625.32 1153,791.79
  rectangle: 1109.68,757 1262,791.79
  rectangle: 1250.14,743.07 1305.88,801
  lines w60: 1599,10 1599,1789

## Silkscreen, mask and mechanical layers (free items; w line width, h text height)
Top Overlay:
  text "Rev A" at 2873,1631 h40
  text "Single-Ended 16-Bit 1MSPS DAQ" at 86,1592 h40
  text "CS0" at 2321,1346 h25
  text "4Wire" at 2003,1262 h25
  text "FSX" at 2296,1150 h25
  text "(MMB0)" at 2259,1111 h25
  text "3Wire" at 2004,1068 h25
  text "JW" at 3039,75 h40
Drill Guide:
  text ".Layer_Name" at 577,-858.49 h60
M1 Board Outline:
  lines w20: 0,1 0,1799 3198,1799 3198,0 1,0
M2 Board Dimensions:
  rectangle: 124.5,-410.5 499.5,-285.5
  rectangle: -0.5,-285.5 124.5,-160.5
  lines w7: -0.5,-285.5 999.5,-285.5 ; 124.5,-410.5 124.5,-160.5 ; 249.5,-410.5 249.5,-160.5 ; 499.5,-410.5 499.5,-160.5 ; 749.5,-410.5 749.5,-160.5 ; -0.5,-410.5 -0.5,-160.5 999.5,-160.5 999.5,-410.5 -0.5,-410.5
  lines w10: -0.5,-475.5 -0.5,-455.5 ; 59.5,-485.5 -0.5,-465.5 ; 59.5,-445.5 -0.5,-465.5 ; 223.58,-465.5 -0.5,-465.5 ; 775.42,-465.5 999.5,-465.5 ; 939.5,-485.5 999.5,-465.5 ; 939.5,-445.5 999.5,-465.5 ; 999.5,-475.5 999.5,-455.5
  text "1000 (mil)" at 233.58,-501.49 h60
  text ".Layer_Name" at 577,-858.49 h60
M3 3D STEP Top:
  text ".Layer_Name" at 577,-858.49 h60
M4 3D STEP Bottom:
  text ".Layer_Name" at 577,-858.49 h60
M5 Assembly Top:
  lines w10: -292,-930.17 6308,-930.17 ; -292,-726.83 6310,-726.83 ; -292,-523.5 -292,-1133.5 3713,-1133.5 6310,-1133.5 6310,-523.5 -291.5,-523.5 -291.5,-1133.5 1284,-1133.5 ; 2173,-1133.5 2173,-523.5 ; 3440,-726.83 3440,-523.5 ; 4280,-726.83 4280,-523.5 ; 4902,-1140 4902,-937.17
  text "COMPONENTS MARKED 'DNP' SHOULD NOT BE POPULATED." at 1153.5,-318.5 h60
  text "ASSEMBLY VARIANT:" at 1153,-434 h60
  text ".VariantName" at 2189,-434 h60
  text "PCB VIEWED FROM TOP SIDE" at -228.5,-655.67 h60
  text "BOARD #:" at 2248,-655.67 h60
  text ".PRJ_Number" at 2793.5,-655.67 h60
  text "REV:" at 3638,-655.67 h60
  text ".PCB_Rev" at 3929.5,-655.67 h60
  text "SVN REV:" at 4476,-655.67 h60
  text ".VersionControl_RevNumber" at 4982,-655.67 h60
  text "IGNORE ->" at -228.5,-858.49 h60
  text "PLOT NAME =" at -228.5,-1064.34 h60
  text ".plot_File_Name" at 577,-1064.34 h60
  text "GENERATED    :" at 2250,-1064.34 h60
  text ".Print_Date" at 3119.5,-1064.34 h60
  text ".Print_Time" at 3848.5,-1064.34 h60
  text "TEXAS INSTRUMENTS" at 5113,-1064.34 h60
M6 Assembly Bottom:
  lines w10: -292.5,-727.33 6309.5,-727.33 ; -290.5,-930.67 6309.5,-930.67 ; 1115.5,-1140.5 1115.5,-937.67 ; 1737.5,-727.33 1737.5,-524 ; 2577.5,-727.33 2577.5,-524 ; 3844.5,-1134 3844.5,-524 ; 4733.5,-1134 6309,-1134 6309,-524 -292.5,-524 -292.5,-1134 2304.5,-1134 6309.5,-1134 6309.5,-524
  text "COMPONENTS MARKED 'DNP' SHOULD NOT BE POPULATED." at 6102,-318 h60
  text ".VariantName" at 5058,-434 h60
  text "ASSEMBLY VARIANT:" at 6097,-434 h60
  text ".VersionControl_RevNumber" at 1035.5,-656.17 h60
  text "SVN REV:" at 1541.5,-656.17 h60
  text ".PCB_Rev" at 2088,-656.17 h60
  text "REV:" at 2379.5,-656.17 h60
  text ".PRJ_Number" at 3224,-656.17 h60
  text "BOARD #:" at 3769.5,-656.17 h60
  text "PCB VIEWED FROM BOTTOM SIDE" at 6246,-656.17 h60
  text "IGNORE ->" at 2547.85,-858.49 h60
  text "TEXAS INSTRUMENTS" at 904.5,-1064.84 h60
  text ".Print_Time" at 2169,-1064.84 h60
  text ".Print_Date" at 2898,-1064.84 h60
  text "GENERATED    :" at 3767.5,-1064.84 h60
  text ".plot_File_Name" at 5440.5,-1064.84 h60
  text "PLOT NAME =" at 6246,-1064.84 h60
M9 Title Sheet:
  drawing of 57 lines, arcs and shapes, not listed
  text "1" at 739.84,8036.5 h70
  text "2" at 3235.5,8036.5 h70
  text "3" at 5724.84,8036.5 h70
  text "4" at 8231.51,8036.5 h70
  text "5" at 10730.5,8036.5 h70
  text "6" at 13235.5,8036.5 h70
  text "A" at -416.5,6893.5 h70
  text "A" at 14383.5,6893.5 h70
  text "PROJECT TITLE:" at 6654,4561.5 h45
  text "B" at -416.5,4513.5 h70
  text "B" at 14383.5,4513.5 h70
  text ".PRJ_Title" at 6704,4428.17 h70
  text "C" at -416.5,2138.5 h70
  text "C" at 14383.5,2138.5 h70
  text "DESIGNED FOR:" at 11343.5,-23.5 h45
  text ".PRJ_Customer" at 11393.5,-163.5 h70
  text "D" at -416.5,-231.5 h70
  text "D" at 14383.5,-231.5 h70
  text "FILE NAME:" at 11343.5,-323.5 h45
  text ".PCB_File_Name_No_Path" at 11393.5,-443.5 h70
  text "Texas Instruments (TI) and/or its licensors do not warrant the accuracy or completeness of this specification" at 6374,-605.34 h45
  text "ENGINEER:" at 11343.5,-613.5 h45
  text "LAYOUT BY:" at 12848.5,-613.5 h45
  text "or any information contained therein. TI and/or its licensors do not warrant that this design will meet" at 6329.01,-718 h45
  text ".PRJ_Engineer" at 11393.5,-768.49 h70
  text ".PCB_Layout" at 12899,-768.49 h70
  text "the specifications, will be suitable for your application or fit for any particular purpose, or will operate in" at 6329.01,-830.67 h45
  text ".Layer_Name" at 577,-858.49 h60
  text "ALTIUM DESIGNER VERSION:" at 12848.5,-923.5 h45
  text "an implementation. TI and/or its licensors do not warrant that the design is production worthy. You should" at 6329.01,-943.33 h45
  text "completely validate and test your design implementation to confirm the system functionality for your application." at 6374,-1056 h45
  text ".print_Scale" at 11393.5,-1056.83 h70
  text ".Application_BuildNumber" at 12899,-1056.83 h70
  text "2" at 3235.5,-1263.5 h70
  text "3" at 5724.84,-1263.5 h70
  text "4" at 8231.51,-1263.5 h70
  text "5" at 10730.5,-1263.5 h70
  text "6" at 13235.5,-1263.5 h70
M10 Fab Notes:
  drawing of 212 lines, arcs and shapes, not listed
  text "DESIGN INFORMATION" at 12381.02,6810 h60
  text "(REFER ALSO ARRAY/PANEL PROFILING INFORMATION)" at 12019.46,6648.29 h60
  text "BOARD SIZE" at 11333.46,6644 h60
  text "3450MIL" at 11795.78,6516.18 h60
  text "X" at 12301.46,6516.18 h60
  text "4950MIL" at 12532.78,6516.18 h60
  text "Number of Layers :" at 11736.46,6319 h60
  text "2" at 12831.27,6309 h60
  text "MIN. TRACK WIDTH:" at 11736.46,6180 h60
  text "8" at 12832.7,6180 h60
  text "MIL" at 12987.46,6180 h60
  text "MIN. CLEARANCE:" at 11736.46,6048 h60
  text "8" at 12832.7,6048 h60
  text "MIL" at 12987.46,6048 h60
  text "MIN. VIA PAD SIZE:" at 11736.46,5916 h60
  text "24" at 12802.71,5916 h60
  text "MIL" at 12987.46,5916 h60
  text "0.05mm (2MIL)" at 12431.46,5774.29 h60
  text "MINIMUM ANNULAR RING" at 11407.23,5770 h60
  text "EXTERNAL" at 13139.46,5770 h60
  text "PER" at 11607.23,5652 h60
  text "IPC-D-275 CLASS 2 LEVEL C" at 11827.23,5652 h60
  text "MIL, HOLES" at 13315.46,5539.71 h60
  text "+/-" at 12923,5539 h60
  text "+/-" at 13777,5539 h60
  text "REGISTRATION TOLERANCES:" at 11407.23,5534 h60
  text "METAL" at 12607,5534 h60
  text "5" at 13183.2,5534 h60
  text "3" at 14016.2,5534 h60
  text "MIL" at 14132.46,5534 h60
  text "MICROSECTION:" at 6625.73,5430.64 h60
  text "YES" at 7531.47,5430.64 h60
  text "REQUIRED" at 8484.96,5398.49 h60
  text "BARE BOARD ELEC. TEST:" at 6717.73,5395.64 h60
  text "NONE" at 8023.47,5395.64 h60
  text "X" at 8357.96,5395.64 h60
  text "PER ORDER" at 9076.96,5395.64 h60
  text "MATERIAL:" at 11332.46,5324.54 h60
  text "MANUFACTURER'S UL:" at 6717.73,5238.64 h60
  text "RAIL" at 7883.47,5234.35 h60
  text "METAL" at 8375.28,5234.35 h60
  text "X" at 8750.5,5234 h60
  text "SILK" at 8886.96,5234.35 h60
  text "FR-4 High Tg" at 12318.9,5184.21 h60
  text "FR-408" at 11753.46,5175.64 h60
  text "X" at 12165.46,5175.64 h60
  text "OTHER" at 13241.46,5175.64 h60
  text "62 MIL (1.6mm) +/-10%" at 12073.56,5012.92 h60
  text "THICKNESS:" at 11407.23,5008.64 h60
  text "X" at 11945.4,5008.64 h60
  text "OTHER" at 13358.46,5008.64 h60
  text "TOLERANCE:" at 11407.23,4850.64 h60
  text "X" at 12246.53,4850.64 h60
  text "ANSI IPC-6012 TYPE 3 CLASS 2" at 12433.48,4850.64 h60
  text "OTHER +/-" at 12433.46,4694.64 h60
  text "BOW & TWIST:" at 11407.23,4537.64 h60
  text "X" at 12246.53,4537.64 h60
  text "ANSI IPC-6012 TYPE 3 CLASS 2" at 12433.48,4537.64 h60
  text "OTHER +/-" at 12433.46,4379.13 h60
  text "COPPER THICKNESS (FINISHED):" at 11332.46,4243.64 h60
  text "1.4MIL (1oz)" at 12212.46,4090.92 h60
  text "2MIL (1.4oz)" at 12979.46,4090.92 h60
  text "2.8MIL (2oz)" at 13706.46,4090.92 h60
  text "OUTER:" at 11689.46,4086.64 h60
  text "X" at 12084,4086 h60
  text "1.4MIL (1oz)" at 12212.46,3933.92 h60
  text "2.8MIL (2oz)" at 12979.46,3933.92 h60
  text "N/A" at 13706,3934.29 h60
  text "INNER SIGNAL:" at 11400.38,3929.64 h60
  text "X" at 12085.42,3929.64 h60
  text "DRILLING:" at 11332.46,3790.64 h60
  text "REFERENCE:" at 11407.23,3673.64 h60
  text "X" at 12055.46,3673.64 h60
  text "AS SHOWN" at 12242.46,3673.64 h60
  text "X" at 12956.46,3673.64 h60
  text "NC_DRILL FILES" at 13093.46,3673.64 h60
  text "PTH MIN COPPER THICKNESS:" at 11407.23,3515.64 h60
  text "X" at 12757.46,3515.64 h60
  text "1MIL" at 12894.46,3515.64 h60
  text "OTHER" at 13391.46,3515.64 h60
  text "BOARD FINISH:" at 11332.46,3356.64 h60
  text "SILKSCREEN:" at 11487.68,3238.64 h60
  text "X" at 12436.46,3238.64 h60
  text "TOP" at 12562.46,3238.64 h60
  text "X" at 12946.46,3238.64 h60
  text "BOTTOM" at 13073.46,3238.64 h60
  text "SILKSCREEN COLOR:" at 11487.68,3071.64 h60
  text "X" at 12435.42,3071.64 h60
  text "WHITE" at 12562.46,3071.64 h60
  text "OTHER" at 13073.46,3071.64 h60
  text "SOLDER RESIST COLOR:" at 11487.68,2901.64 h60
  text "X" at 12055.42,2742.44 h60
  text "GREEN" at 12182.46,2742.44 h60
  text "BLUE" at 12773.46,2742.44 h60
  text "OTHER" at 13311.46,2742.44 h60
  text "IMMERSION GOLD (ENIG)" at 12393.46,2553.92 h60
  text "ENEPIG" at 13731,2550.64 h60
  text "SURFACE FINISH:" at 11332.46,2549.64 h60
  text "X" at 12206.51,2549.64 h60
  text "IMM. TIN/SILVER OR EQUIV" at 11662,2392.64 h60
  text "OTHER" at 13093.46,2392.64 h60
  text "ARRAY/PANEL:" at 11332.46,2213.64 h60
  text "CUT AND TRIM PER MECH LAYER 1" at 12393.46,2209.35 h60
  text "N.C. ROUTE" at 12393.46,2057.64 h60
  text "X" at 13072.46,2057.64 h60
  text "V. SCORE" at 13259.46,2057.64 h60
  text "CERTIFICATION:" at 11332.46,1920.64 h60
  text "MATERIALS AND WORKMANSHIP FOR ALL PCBS" at 12057.46,1920.64 h60
  text "TO MEET OR EXCEED THE REQUIREMENTS OF:" at 12057.46,1822.64 h60
  text "X" at 11683.96,1686.13 h60
  text "ANSI IPC-A-600F CLASS ->" at 11822.96,1686.13 h60
  text "X" at 13462.02,1686.13 h60
  text "2" at 13580.96,1686.14 h60
  text "1" at 13265.96,1684.64 h60
  text "3" at 13934.96,1684.64 h60
  text "X" at 11686.02,1526.64 h60
  text "UL 94V-0" at 11822.96,1526.64 h60
  text "X" at 12498.02,1526.64 h60
  text "RoHS" at 12634.96,1526.64 h60
  text "OTHER" at 13279.36,1526.64 h60
  text "PER ORDER" at 13676.42,1526.64 h60
  text "ADDITIONAL REQUIREMENTS:" at 11332.46,1385.64 h60
  text ".Layer_Name" at 577,-858.49 h60
M11 Gerber Information:
  lines w10: -292,-930.17 6308,-930.17 ; -292,-726.83 6310,-726.83 ; -292,-523.5 -292,-1133.5 3713,-1133.5 6310,-1133.5 6310,-523.5 -291.5,-523.5 -291.5,-1133.5 1284,-1133.5 ; 2173,-1133.5 2173,-523.5 ; 3440,-726.83 3440,-523.5 ; 4280,-726.83 4280,-523.5 ; 4902,-1140 4902,-937.17
  text "ALL ARTWORK VIEWED FROM TOP SIDE" at -228.5,-655.67 h60
  text "BOARD #:" at 2248,-655.67 h60
  text ".PRJ_Number" at 2793.5,-655.67 h60
  text "REV:" at 3638,-655.67 h60
  text ".PCB_Rev" at 3929.5,-655.67 h60
  text "SVN REV:" at 4476,-655.67 h60
  text ".VersionControl_RevNumber" at 4982,-655.67 h60
  text "LAYER NAME =" at -228.5,-858.49 h60
  text "PLOT NAME =" at -228.5,-1064.34 h60
  text ".plot_File_Name" at 577,-1064.34 h60
  text "GENERATED    :" at 2250,-1064.34 h60
  text ".Print_Date" at 3119.5,-1064.34 h60
  text ".Print_Time" at 3848.5,-1064.34 h60
  text "TEXAS INSTRUMENTS" at 5113,-1064.34 h60
M12 Stackup:
  lines w6: 11360,7460 13910,7460 ; 11360,7564.4 13910,7564.4 ; 11300,6975 ccw(c11334,6975) 11334,6941 13936,6941 ccw(c13936,6975) 13970,6975 13970,7681 ccw(c13936,7681) 13936,7715 11334,7715 ccw(c11334,7681) 11300,7681 11300,6975
  text "The Stackup Legend below this is static." at 11605.5,7874.5 h60
  text "If you change the stackup, update the Legend." at 11615.5,7784.5 h60
  text "Layer Stack Up Detail for: Ref_Design.PcbDoc" at 11360,7597.1 h57
  text "Layer" at 11360,7525.4 h24
  text "Gerber" at 12255.81,7525.4 h24
  text "Copper" at 12819.33,7525.4 h24
  text "Dielectric" at 13422.04,7525.4 h24
  text "Name" at 11360,7477.4 h24
  text "Document" at 12255.81,7477.4 h24
  text "Thickness" at 12819.33,7477.4 h24
  text "Material" at 13422.04,7477.4 h24
  text "Top Solder Mask" at 11360,7384.44 h34
  text "(.GTS)" at 12255.81,7384.44 h34
  text "Solder Resist" at 13422.04,7384.44 h34
  text "Top Layer" at 11360,7287.69 h34
  text "(.GTL)" at 12255.81,7287.69 h34
  text "1.4mil" at 12819.33,7287.69 h34
  text "FR-4" at 13422.04,7239.31 h34
  text "Bottom Layer" at 11360,7190.94 h34
  text "(.GBL)" at 12255.81,7190.94 h34
  text "1.4mil" at 12819.33,7190.94 h34
  text "Bottom Solder Mask" at 11360,7094.19 h34
  text "(.GBS)" at 12255.81,7094.19 h34
  text "Solder Resist" at 13422.04,7094.19 h34
M13 Component Bodies Top:
  text ".Layer_Name" at 577,-858.49 h60
M14 Component Bodies Bottom:
  text ".Layer_Name" at 577,-858.49 h60
M15 Courtyards Top:
  text ".Layer_Name" at 577,-858.49 h60
M16 Courtyards Bottom:
  text ".Layer_Name" at 577,-858.49 h60
Drill Drawing:
  text ".legend" at 433,5009.5 h60
  text "Drill Table" at 458,4824.5 h60
  text ".Layer_Name" at 577,-858.49 h60

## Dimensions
-3209.65,18.7 to -3209.65,1818.7 on M2 Board Dimensions
0,0 to 3200,0 on M2 Board Dimensions
0,0 to 0,1800 on M2 Board Dimensions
